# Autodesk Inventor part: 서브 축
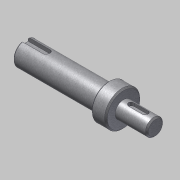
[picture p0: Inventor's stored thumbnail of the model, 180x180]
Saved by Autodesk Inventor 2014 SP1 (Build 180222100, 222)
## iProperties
Created: 2016-04
Part Number: 서브 축
Document SubType Name: Modeling
Designer: mdu
Density: 1 g/cm^3
Mass: 19.9624 g
Surface Area: 57.7178 cm^2
Volume: 19.9624 cm^3
Material: 강철, 연강
Appearance: 금속-강(스테인리스, 브러시됨)
Author: mdu
Revision Number: 1
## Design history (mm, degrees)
sketch "스케치1"
  geometry: L1 (-16.331, 0)-(-108.831, 0); L2 (-16.331, 0)-(-16.331, -6); L3 (-16.331, -6)-(-38.831, -6); L4 (-38.831, -12.5)-(-46.5, -12.5); L5 (-46.5, -8.5)-(-108.831, -8.5); L6 (-108.831, -8.5)-(-108.831, 0); L7 (-46.5, -8.5)-(-46.5, -12.5); L8 (-38.831, -6)-(-38.831, -12.5); L9 (-46.5, 12.249)-(-46.5, -12.249) reference; L10 (-38.831, -17)-(-38.831, 17) reference; 2 further points
  constraints: 17 end point, 4 perpendicular, 2 collinear, 2 parallel, 1 horizontal, 1 midpoint, 1 point on line
  dimensions: "d1" = 12 diameter of L3 L1; "d2" = 25 diameter of L4 L1; "d3" = 17 diameter of L5 L1; "d18" = 22.5 distance of L2.end L3.end; "d20" = 70 distance between parallel lines of L6 L8; "d21" = 7.66872 distance of L4.start L4.end (derived)
revolve "회전1" sketch "스케치1" stored, may be unused: angle "d5" = 90 deg
chamfer "모따기1" distance "d6" = 1; stored, may be unused: second distance "d7" = 2, angle "d8" = 45 deg
node "작업 평면1"
sketch "스케치2"
  geometry: L1 (11.25, 5)-(11.25, -5) reference; L2 (-5.75, -2)-(4.25, -2); L3 (4.25, 2)-(-5.75, 2); A1 r 2 centre (4.25, 0) between (4.25, -2) and (4.25, 2); A2 r 2 centre (-5.75, 0) between (-5.75, 2) and (-5.75, -2); 2 further points
  constraints: 4 end point, 4 point on circle, 4 tangent, 2 centre point, 1 horizontal alignment, 1 midpoint, 1 parallel, 1 perpendicular
  dimensions: "d9" = 4 distance between parallel lines of L2 L3; "d10" = 14 dimension on A1 A2; "d11" = 5 distance edge to line of A1 L1
extrude "돌출1" cut sketch "스케치2" distance "d12" = 2.5; taper "d13" = 0 deg
node "작업 평면2"
sketch "스케치3"
  geometry: L1 (-31.166, -7.5)-(-31.166, 7.5) reference; L2 (-31.166, 2.5)-(-15.666, 2.5); L3 (-15.666, -2.5)-(-31.166, -2.5); A1 r 2.5 centre (-15.666, 0) between (-15.666, -2.5) and (-15.666, 2.5); 2 further points
  constraints: 4 end point, 2 perpendicular, 2 point on circle, 2 point on line, 2 tangent, 1 centre point, 1 horizontal alignment, 1 midpoint
  dimensions: "d14" = 5 distance between parallel lines of L3 L2; "d15" = 18 dimension on A1 L1
extrude "돌출2" cut sketch "스케치3" distance "d16" = 3; taper "d17" = 0 deg
sketch "스케치4"
  geometry: C1 r 12.5 at (0, 0) reference; 1 further point
extrude "돌출3" join sketch "스케치4" distance "d22" = 3; taper "d23" = 0 deg
chamfer "모따기2" distance "d24" = 1; stored, may be unused: second distance "d25" = 2, angle "d26" = 45 deg
node "솔리드1"
node "참조4"
node "참조5"
